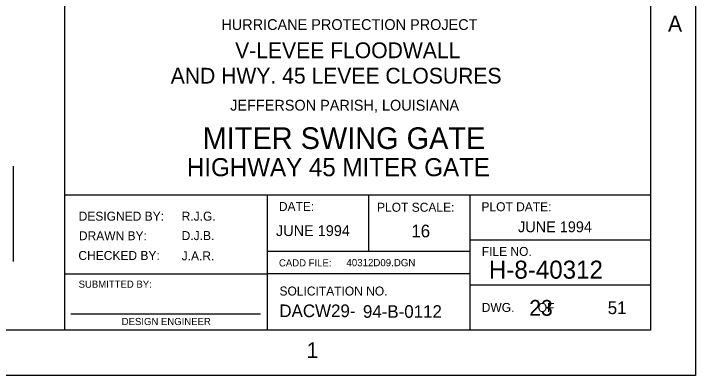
# Model space of a CAD drawing. Extents: x 0.6 to 54, y 0.6 to 38.
# Drawn here: x 43.87 to 53.96, y 0.63 to 5.98 of the extents above; entities that cross this region are included whole.
import ezdxf

# ---------------------------------------------------------------- set-up
doc = ezdxf.new("R2010")
doc.units = 0
doc.layers.add('Level 1', color=7, linetype='Continuous')
doc.layers.add('Level 2', color=7, linetype='Continuous')

msp = doc.modelspace()

# ---------------------------------------------------------------- linework, layer by layer
at = {"layer": 'Level 1'}
for p, q in [((44.625, 1.292), (44.625, 7.625)), ((43.866, 2.311), (43.866, 3.719)), ((53.292, 3.292), (44.625, 3.292)), ((47.625, 1.292), (47.625, 3.292)), ((49.125, 2.458), (49.125, 3.292)), ((50.625, 1.292), (50.625, 3.292)), ((53.292, 2.625), (50.625, 2.625)), ((50.625, 2.458), (47.625, 2.458)), ((44.625, 2.125), (47.625, 2.125)), ((50.625, 2.125), (47.625, 2.125)), ((53.292, 1.958), (50.625, 1.958)), ((44.715, 1.536), (47.519, 1.536))]:
    msp.add_line(p, q, dxfattribs=at)
for points in [[(0.625, 37.958), (53.958, 37.958), (53.958, 0.625), (0.625, 0.625)], [(2.625, 37.292), (53.292, 37.292), (53.292, 1.292), (2.625, 1.292)]]:
    msp.add_lwpolyline(points, close=True, dxfattribs=at)

# ---------------------------------------------------------------- texts
for s, height, p in [('A', 0.234, (53.553, 5.71)), ('DATE:', 0.1328, (47.793, 3.057)), ('PLOT SCALE:', 0.13283, (49.246, 3.045)), ('PLOT DATE:', 0.1328, (50.792, 3.053)), ('DESIGNED BY:', 0.13283, (44.829, 2.913)), ('DRAWN BY:', 0.1328, (44.832, 2.624)), ('FILE NO.', 0.1328, (50.796, 2.392)), ('CHECKED BY:', 0.13283, (44.825, 2.332)), ('CADD FILE:', 0.1057, (47.794, 2.236)), ('SUBMITTED BY:', 0.10567, (44.828, 1.921)), ('SOLICITATION NO.', 0.13283, (47.802, 1.806)), ('DACW29-', 0.1872, (47.8, 1.486)), ('DWG.       OF', 0.13283, (50.796, 1.563)), ('DESIGN ENGINEER', 0.10567, (45.466, 1.369)), ('1', 0.234, (48.202, 0.88))]:
    msp.add_text(s, height=height, dxfattribs=at).set_placement(p)
at = {"layer": 'Level 2'}
for s, height, p in [('HURRICANE PROTECTION PROJECT', 0.16, (46.941, 5.734)), ('V-LEVEE FLOODWALL', 0.23367, (47.145, 5.317)), ('AND HWY. 45 LEVEE CLOSURES', 0.23367, (46.192, 4.941)), ('JEFFERSON PARISH, LOUISIANA', 0.16, (47.072, 4.541)), ('MITER SWING GATE', 0.32, (46.665, 3.974)), ('HIGHWAY 45 MITER GATE', 0.26717, (46.431, 3.571)), ('R.J.G.', 0.1328, (46.354, 2.913)), ('JUNE 1994', 0.16, (47.75, 2.686)), ('16', 0.1872, (49.753, 2.667)), ('JUNE 1994', 0.16, (51.333, 2.742)), ('D.J.B.', 0.1328, (46.354, 2.626)), ('J.A.R.', 0.1328, (46.354, 2.326)), ('40312D09.DGN', 0.10717, (48.793, 2.239)), ('H-8-40312', 0.2672, (50.902, 2.055)), ('23', 0.2337, (51.499, 1.507)), ('51', 0.1872, (52.661, 1.531)), ('94-B-0112', 0.1872, (49.037, 1.476))]:
    msp.add_text(s, height=height, dxfattribs=at).set_placement(p)

doc.saveas('drawing.dxf')
